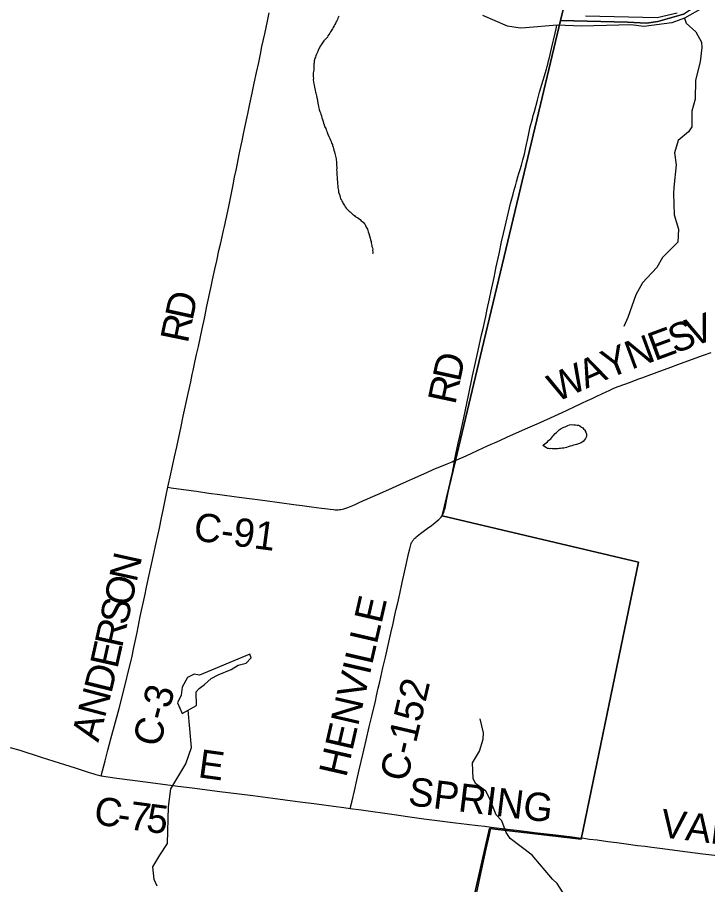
# Model space of a CAD drawing. Extents: x 1410790 to 1770854, y 448063 to 770588.
# Drawn here: x 1562316 to 1569641, y 582392 to 591590 of the extents above; entities that cross this region are included whole.
import ezdxf

# ---------------------------------------------------------------- set-up
doc = ezdxf.new("R2010")
doc.units = 0
for name, color, linetype in [('GM_X_County_Road', 7, 'Continuous'), ('GM_X_County_Road_Text', 7, 'Continuous'), ('GM_X_Major_River', 7, 'Continuous'), ('GM_X_Minor_Lake', 7, 'Continuous'), ('GM_X_Minor_River', 7, 'Continuous'), ('GM_X_Township', 7, 'Continuous'), ('GM_X_Township_Road', 7, 'Continuous')]:
    doc.layers.add(name, color=color, linetype=linetype)

msp = doc.modelspace()

# ---------------------------------------------------------------- linework, layer by layer
at = {"layer": 'GM_X_County_Road'}
for points in [[(1563913.9, 586607.1), (1563945.2, 586749.3), (1563955.8, 586797.3), (1563984.2, 586928.8), (1564007.2, 587034.5), (1564054, 587252.6), (1564076.9, 587361.8), (1564127.9, 587599.1), (1564155.7, 587723.9), (1564172.5, 587801), (1564182, 587845.7), (1564200.6, 587932.3), (1564218.5, 588015.5), (1564236.8, 588098.7), (1564278.9, 588287.6), (1564300.8, 588397.1), (1564328, 588528.7), (1564371.7, 588734), (1564387.4, 588807.7), (1564411.8, 588919.8), (1564431.1, 589009.1), (1564455.1, 589118.1), (1564474.2, 589199.8), (1564503.5, 589328.1), (1564513.6, 589372.5), (1564549.7, 589536.1), (1564562.9, 589603.1), (1564605.5, 589812.3), (1564621.1, 589895.6), (1564636.8, 589969.4), (1564650.7, 590040.2), (1564670.3, 590136.5), (1564691.4, 590232.6), (1564701.7, 590280.6), (1564716.8, 590354.3), (1564726.5, 590402.4), (1564740.3, 590469.8), (1564760.7, 590566), (1564783.5, 590672.4), (1564807.4, 590784), (1564830.6, 590893), (1564854.4, 591005.2), (1564877.3, 591111.1), (1564895.3, 591197.8), (1564911.4, 591281.5), (1564927.9, 591355.1), (1564941.1, 591415.9), (1564970.2, 591550.6), (1564987.3, 591637.4)], [(1566955.8, 586887.9), (1566968.7, 586956.3), (1566994.5, 587075), (1567010.6, 587148.7), (1567052.3, 587344.4), (1567102.2, 587578.6), (1567147, 587787.2), (1567178.5, 587928), (1567205.8, 588056.4), (1567242.7, 588223), (1567258, 588290.2), (1567285.8, 588418.4), (1567302.8, 588495.3), (1567327, 588604.1), (1567345.2, 588690.8), (1567367.6, 588800), (1567374.2, 588832.1), (1567397.9, 588944.4), (1567427.5, 589082.3), (1567454.9, 589210.7), (1567474.1, 589297), (1567502.3, 589418.4), (1567549.8, 589616.3), (1567576, 589714.6), (1567588.2, 589759), (1567600.5, 589803.2), (1567612, 589844.2), (1567627.3, 589897.7), (1567638.5, 589935.3), (1567650.8, 589976), (1567664.5, 590023.2), (1567680.1, 590080.1), (1567696, 590140.2), (1567716.8, 590225.9), (1567733.9, 590305.7), (1567759.3, 590427.6), (1567781.9, 590513.3), (1567791.4, 590548), (1567803.5, 590592.2), (1567835.3, 590712.5), (1567858.6, 590798), (1567894.5, 590924.4), (1567929.9, 591040), (1567937.9, 591068.6), (1567944.7, 591094.7), (1567954, 591129.7), (1567961.9, 591162.3), (1567985.7, 591259.6), (1568022.6, 591420.7), (1568033.2, 591467), (1568042.6, 591506.4)], [(1566955.8, 586887.9), (1567078, 586941.1), (1567260.1, 587024.1), (1567304.8, 587044.6), (1567343.5, 587062.4), (1567379.4, 587078.5), (1567436.4, 587103.9), (1567517.4, 587139.7), (1567733.2, 587235.3), (1567831.8, 587279.9), (1567972.3, 587343.4), (1568142.6, 587420.3), (1568166.2, 587431.4), (1568225.3, 587459.6), (1568305.2, 587497.5), (1568367.5, 587526.6), (1568415.1, 587548.8), (1568459.6, 587569.6), (1568518.7, 587598), (1568563, 587619.2), (1568595.7, 587634.2), (1568637.7, 587652.6), (1568680, 587670.2), (1568772, 587704.7), (1568839.5, 587729.5), (1568901, 587752.5), (1568953.3, 587771.9), (1569135.1, 587837.8), (1569221.1, 587870.2), (1569353.7, 587918.6), (1569402.9, 587936.3), (1569507.5, 587973.9), (1569598.8, 588007.3), (1569678.8, 588036.7)], [(1563913.9, 586607.1), (1563946.5, 586602.2), (1564079.4, 586582.4), (1564215.9, 586563.5), (1564349.1, 586545.7), (1564462.9, 586530.6), (1564641.6, 586505.7), (1564947.2, 586465.2), (1565096.7, 586445.1), (1565249.4, 586424.4), (1565337, 586412.6), (1565437.9, 586400.1), (1565541.9, 586385.9), (1565577.7, 586380.8), (1565636, 586373.3), (1565671.8, 586369.8), (1565688.8, 586368.7), (1565707.1, 586367.7), (1565719.8, 586368.3), (1565733.3, 586369.6), (1565750.2, 586371.6), (1565765.2, 586374.2), (1565780.9, 586378.1), (1565800.5, 586384.4), (1565823.7, 586392.5), (1565875.2, 586413.3), (1565908.3, 586427.4), (1565944.2, 586443.5), (1565983.1, 586460.9), (1566024.8, 586479.8), (1566063.4, 586497.5), (1566161.8, 586541.6), (1566296.7, 586601), (1566374.6, 586635.8), (1566446.6, 586667.6), (1566509.8, 586695), (1566629.7, 586748.1), (1566761.4, 586807.3), (1566770.3, 586811.4), (1566797.5, 586822.9), (1566876.1, 586855.9), (1566930.9, 586877.9), (1566949, 586885.1), (1566955.8, 586887.9)], [(1566826.7, 586307.6), (1566829.1, 586311.5), (1566836.2, 586324.1), (1566841.9, 586337.8), (1566850, 586365.6), (1566855.1, 586384.4), (1566859.1, 586403.3), (1566874.6, 586480.1), (1566913.8, 586673), (1566931.9, 586763), (1566950.5, 586859.5), (1566955.8, 586887.9)], [(1563206, 583546.9), (1563246.6, 583706.9), (1563275.3, 583817.9), (1563307.9, 583937.9), (1563395, 584261), (1563463.9, 584524.5), (1563496.5, 584658.4), (1563529.1, 584798.5), (1563552.8, 584908.1), (1563585.7, 585066.3), (1563620.9, 585235.8), (1563671.5, 585473.1), (1563683.8, 585530.9), (1563708.3, 585646.3), (1563742.6, 585806.6), (1563789.3, 586018), (1563823.2, 586171.8), (1563846.9, 586284.1), (1563863.1, 586364.5), (1563895.2, 586521.9), (1563913.9, 586607.1)], [(1565848.8, 583200.6), (1565867.8, 583281.7), (1565892.5, 583387.4), (1565919.7, 583502.2), (1565944.7, 583610.9), (1565982.9, 583773.5), (1566018.3, 583923.8), (1566050.9, 584064.4), (1566081.1, 584192.1), (1566115.6, 584339.1), (1566128.1, 584393.4), (1566146.5, 584476.6), (1566161.3, 584543.8), (1566194.4, 584691.1), (1566221.5, 584806.1), (1566244.4, 584901.8), (1566280.5, 585058.4), (1566303.3, 585160.8), (1566323.3, 585250.3), (1566337.1, 585314.3), (1566352.1, 585381.5), (1566374, 585477.5), (1566400.7, 585595.1), (1566425.8, 585705.6), (1566470.7, 585913), (1566479.8, 585952.3), (1566487.6, 585983.3), (1566491.1, 585996.1), (1566495.4, 586008.7), (1566500, 586019.6), (1566504, 586027.3), (1566508.6, 586034.5), (1566513.2, 586041.5), (1566518.3, 586048.5), (1566523.6, 586054.8), (1566529.7, 586061.7), (1566535.2, 586067.1), (1566543.2, 586074.5), (1566549.5, 586080.5), (1566557.2, 586087.4), (1566593.6, 586115.7), (1566664.8, 586168.1), (1566709.5, 586201.3), (1566744.7, 586229), (1566774.7, 586253.4), (1566787.9, 586263.7), (1566799.3, 586274.3), (1566812.5, 586288.6), (1566821.9, 586299.7), (1566826.7, 586307.6)], [(1562241.3, 583848.3), (1562341.4, 583816.9), (1562569.8, 583744.6), (1562704.4, 583702.6), (1562816.9, 583666.5), (1562929.4, 583630.6), (1563034.9, 583596.2), (1563077, 583582.7), (1563117.3, 583570.5), (1563148.7, 583561.8), (1563206, 583546.9)], [(1563206, 583546.9), (1563372.7, 583522.6), (1563674.9, 583481.9), (1564019.3, 583437.7), (1564172, 583417.6), (1564464.8, 583380.6), (1564670.1, 583356.1), (1564816.4, 583337.7), (1565027.7, 583310), (1565287.8, 583275.4), (1565489.4, 583248.3), (1565671.4, 583223.5), (1565782, 583209), (1565848.8, 583200.6)], [(1565848.8, 583200.6), (1565963.8, 583185.5), (1566314.4, 583137.8), (1566456.8, 583116.4), (1566630.6, 583090.8), (1566716, 583078.8), (1566966.6, 583047.2), (1567087.1, 583033.4), (1567201, 583020.4), (1567275.8, 583011.7), (1567343.1, 583003.4)], [(1567343.1, 583003.4), (1567516.1, 582982), (1567613.8, 582970.5), (1567724.5, 582956.9), (1567802.6, 582947.1), (1567900.1, 582934.9), (1568030.4, 582919.8), (1568115.1, 582909.9), (1568203.1, 582899.4), (1568274.7, 582890.7), (1568328.3, 582884)], [(1568328.3, 582884), (1568388.5, 582876.6), (1568469.8, 582866.3), (1568580.3, 582851.5), (1568677.7, 582837.8), (1568775.3, 582824.8), (1568895.5, 582809.4), (1568976.9, 582799.5), (1569048.5, 582790.5), (1569162.2, 582774.8), (1569345.5, 582751.4), (1569591.4, 582720.1), (1569901.7, 582683), (1570047.7, 582665), (1570157.3, 582650), (1570322.5, 582626.7), (1570430.7, 582613.1), (1570590.3, 582592.9), (1570871.8, 582557.9)]]:
    msp.add_lwpolyline(points, dxfattribs=at)
at = {"layer": 'GM_X_Major_River'}
for points in [[(1569621.7, 591707.7), (1569394, 591580.4), (1569260.4, 591531.4), (1568962.4, 591492.1), (1568826.4, 591511.3), (1568699.8, 591506.2), (1568302.2, 591495.2), (1568043.5, 591507.2), (1567707.7, 591478.9), (1567653.4, 591476.1), (1567517.4, 591497.3), (1567257.1, 591609.7)], [(1569319, 591634.4), (1569107, 591583.1), (1568346.8, 591602.6)]]:
    msp.add_lwpolyline(points, dxfattribs=at)
at = {"layer": 'GM_X_Minor_Lake'}
for points in [[(1567891.1, 587050.4), (1567897.6, 587057.6), (1567942, 587089.3), (1567952.2, 587103.3), (1567966.3, 587113.3), (1567976.3, 587119.2), (1567986.5, 587135.2), (1567998.6, 587147.2), (1568006.7, 587157.1), (1568024.9, 587177.1), (1568037, 587187), (1568051.2, 587203), (1568065.3, 587214.9), (1568077.4, 587222.8), (1568087.5, 587228.8), (1568101.6, 587236.7), (1568115.7, 587242.6), (1568127.8, 587246.6), (1568141.9, 587254.5), (1568156, 587262.4), (1568176.1, 587268.3), (1568198.2, 587272.2), (1568220.3, 587268), (1568240.4, 587269.8), (1568256.4, 587265.7), (1568270.4, 587265.6), (1568284.4, 587257.5), (1568302.4, 587245.3), (1568318.4, 587235.2), (1568324.4, 587225.1), (1568340.4, 587212.9), (1568342.3, 587202.9), (1568348.2, 587190.8), (1568354.1, 587168.7), (1568354, 587156.6), (1568353.9, 587144.6), (1568343.8, 587124.6), (1568333.6, 587110.6), (1568319.5, 587090.7), (1568297.3, 587078.8), (1568271.1, 587066.9), (1568251, 587061), (1568234.9, 587057.2), (1568216.8, 587051.3), (1568198.7, 587045.4), (1568180.6, 587041.5), (1568160.5, 587035.6), (1568144.4, 587029.7), (1568128.3, 587025.8), (1568114.2, 587019.9), (1568096.1, 587020), (1568080, 587016.1), (1568066, 587016.2), (1568051.9, 587014.3), (1568037.9, 587012.4), (1568027.8, 587012.5), (1568017.8, 587012.5), (1567999.7, 587012.7), (1567989.7, 587014.8), (1567975.7, 587016.9), (1567963.6, 587014.9), (1567953.6, 587017), (1567943.5, 587019.1), (1567931.6, 587025.2), (1567891.1, 587050.4)], [(1564218.7, 584293.3), (1564211.8, 584437.9), (1564246.6, 584473.2), (1564303.6, 584513.9), (1564371.1, 584578.6), (1564448, 584616.9), (1564585.5, 584675.8), (1564658.6, 584720.2), (1564745.2, 584742.3), (1564798.5, 584797.2), (1564781.3, 584837.7), (1564247.6, 584615.5), (1564191.7, 584622.9), (1564120.8, 584588.4), (1564066.6, 584487.4), (1564052.7, 584401.5), (1564016.9, 584322.1), (1564064.6, 584208.6)], [(1564064.6, 584208.6), (1564218.7, 584293.3)]]:
    msp.add_lwpolyline(points, dxfattribs=at)
at = {"layer": 'GM_X_Minor_River'}
for points in [[(1565727.8, 591602.8), (1565717.6, 591580.8), (1565713.5, 591566.8), (1565705.4, 591552.8), (1565697.3, 591538.8), (1565691.2, 591524.8), (1565685.1, 591512.8), (1565676.9, 591498.8), (1565666.8, 591480.8), (1565660.7, 591466.8), (1565654.6, 591456.8), (1565646.5, 591446.8), (1565640.4, 591434.8), (1565632.2, 591420.9), (1565622.1, 591406.9), (1565612, 591392.9), (1565605.9, 591380.9), (1565593.7, 591366.9), (1565583.6, 591355), (1565569.5, 591339), (1565561.4, 591329), (1565555.3, 591319.1), (1565539.1, 591297.1), (1565528.9, 591283.1), (1565524.9, 591273.1), (1565518.7, 591261.1), (1565510.6, 591249.1), (1565506.6, 591239.1), (1565504.5, 591227.1), (1565496.3, 591213.1), (1565490.2, 591199.1), (1565484.1, 591183.1), (1565480, 591169.1), (1565473.9, 591155.1), (1565469.7, 591139.1), (1565465.7, 591129.1), (1565465.6, 591119), (1565465.5, 591109), (1565461.4, 591097), (1565461.4, 591084.9), (1565461.3, 591074.9), (1565461.2, 591060.8), (1565461.1, 591044.8), (1565461, 591030.8), (1565458.9, 591014.7), (1565456.8, 591000.7), (1565456.7, 590990.6), (1565454.5, 590968.6), (1565456.5, 590958.5), (1565458.4, 590944.5), (1565456.3, 590926.4), (1565458.1, 590904.3), (1565462, 590884.2), (1565465.9, 590870.2), (1565467.8, 590850.1), (1565471.7, 590832), (1565477.6, 590815.9), (1565479.5, 590797.8), (1565483.4, 590785.8), (1565487.4, 590771.7), (1565491.3, 590757.6), (1565493.2, 590739.5), (1565497.1, 590727.4), (1565504.8, 590679.2), (1565506.7, 590663.2), (1565510.6, 590647.1), (1565514.5, 590627), (1565520.4, 590610.9), (1565526.3, 590592.8), (1565532.2, 590578.7), (1565536.1, 590562.6), (1565542, 590546.5), (1565547.9, 590524.4), (1565553.8, 590506.3), (1565559.7, 590484.2)], [(1569394, 591580.4), (1569414.3, 591528.8), (1569516.5, 591436.1), (1569574.3, 591326.5), (1569581.1, 591268.2), (1569561.8, 591116.2), (1569511.6, 590922.8), (1569509.3, 590722.3), (1569472.5, 590594.8), (1569475, 590430.2), (1569439.8, 590376.9), (1569327.6, 590283.2), (1569290.8, 590153.7), (1569306, 590025), (1569280.9, 589786.9), (1569279.5, 589722.8), (1569286.7, 589495.9), (1569333.5, 589342.4), (1569324.6, 589206.2), (1569162.8, 589043.5), (1569100.4, 588936.7), (1568948.7, 588773.8), (1568877.8, 588647), (1568794.6, 588408.3), (1568751.6, 588312.6)], [(1565559.7, 590484.2), (1565565.6, 590466.1), (1565573.5, 590449.9), (1565575.4, 590433.9), (1565583.4, 590421.8), (1565589.3, 590409.7), (1565593.2, 590395.6), (1565599.2, 590383.5), (1565605.1, 590369.4), (1565611, 590351.3), (1565622.9, 590325.2), (1565630.8, 590305), (1565638.7, 590288.9), (1565644.6, 590272.8), (1565650.5, 590256.7), (1565658.5, 590240.6), (1565660.4, 590230.6), (1565668.3, 590212.4), (1565670.2, 590198.4), (1565674.1, 590180.3), (1565682, 590162.2), (1565685.9, 590146.1), (1565689.8, 590130), (1565691.7, 590115.9), (1565695.7, 590103.9), (1565697.6, 590089.8), (1565699.5, 590073.7), (1565701.4, 590061.7), (1565703.3, 590049.6), (1565703.2, 590033.6), (1565703.1, 590019.5), (1565705, 590001.4), (1565704.9, 589989.4), (1565702.8, 589971.4), (1565704.7, 589957.3), (1565706.6, 589943.2), (1565704.5, 589927.2), (1565710.2, 589883), (1565708.1, 589867), (1565712, 589848.9), (1565713.9, 589824.8), (1565717.8, 589804.7), (1565717.6, 589784.6), (1565721.5, 589768.5), (1565725.4, 589754.4), (1565725.3, 589734.4), (1565731.2, 589718.3), (1565737.1, 589700.2), (1565741, 589684.1), (1565746.9, 589666), (1565754.9, 589653.9), (1565760.8, 589641.8), (1565768.8, 589627.7), (1565774.7, 589615.6), (1565780.7, 589605.5), (1565788.6, 589593.4), (1565794.5, 589579.3), (1565806.5, 589567.2), (1565816.5, 589555.1), (1565826.4, 589545), (1565836.4, 589534.9), (1565846.4, 589526.8), (1565864.3, 589510.6), (1565874.3, 589500.5), (1565884.3, 589494.4), (1565894.3, 589488.3), (1565902.3, 589478.2), (1565914.3, 589472.1), (1565926.3, 589466), (1565944.3, 589451.8), (1565954.3, 589447.7), (1565966.2, 589433.6), (1565976.2, 589425.5), (1565986.2, 589419.4), (1565998.1, 589401.3), (1566006.1, 589391.2), (1566012, 589381.1), (1566018, 589365), (1566025.9, 589354.9), (1566029.9, 589344.8), (1566033.8, 589330.8), (1566037.7, 589316.7), (1566045.6, 589296.6), (1566059.3, 589246.3), (1566065.2, 589230.2), (1566069.1, 589214.1), (1566071, 589198), (1566075, 589184), (1566078.9, 589171.9), (1566078.8, 589159.9), (1566084.7, 589143.8), (1566086.6, 589129.7), (1566084.5, 589115.7), (1566086.5, 589103.6), (1566088.4, 589093.6), (1566086.3, 589083.5)], [(1563801, 582375.4), (1563768.5, 582446.3), (1563755.4, 582583.1), (1563828.1, 582705.7), (1563910.9, 582828.2), (1563919.2, 583217.1), (1563945.3, 583409.1), (1564103.2, 583672.2), (1564165, 583845.2), (1564128.4, 584243.7)], [(1568163.3, 582217), (1568045.1, 582404.4), (1567994, 582451.7), (1567779, 582703.5), (1567546.4, 582881.4), (1567501.7, 582944.6), (1567458.3, 583070), (1567395.5, 583133.7), (1567325.2, 583309.8), (1567288.7, 583382.9), (1567176.2, 583463.8), (1567151.3, 583518.5), (1567146.9, 583685.1), (1567221.6, 583809.7), (1567258.4, 583935.2), (1567261.8, 584003.3), (1567226.9, 584150.6)]]:
    msp.add_lwpolyline(points, dxfattribs=at)
at = {"layer": 'GM_X_Township'}
for points in [[(1568287, 592416.8), (1568080.9, 591556), (1567885.2, 590738.6), (1567559.7, 589379.4), (1567265.9, 588152.5), (1566963.9, 586891.4), (1566823.2, 586303.6), (1568906.4, 585811.5), (1568300.4, 582874.8), (1567328, 582988.6), (1566849.4, 580884.8)], [(1569383.7, 591622.7), (1569112.2, 591544.6), (1568993.7, 591527.4), (1568789.1, 591539.1), (1568080.9, 591556), (1568287, 592416.8)], [(1566849.4, 580884.8), (1567328, 582988.6), (1568300.4, 582874.8), (1568906.4, 585811.5), (1566823.2, 586303.6), (1566963.9, 586891.4), (1567265.9, 588152.5), (1567559.7, 589379.4), (1567885.2, 590738.6), (1568080.9, 591556), (1568789.1, 591539.1), (1568993.7, 591527.4), (1569112.2, 591544.6), (1569383.7, 591622.7), (1569593.4, 591763.5), (1569704.6, 591866.9)]]:
    msp.add_lwpolyline(points, dxfattribs=at)
at = {"layer": 'GM_X_Township_Road'}
msp.add_lwpolyline([(1566891.5, 580915.9), (1566889.6, 580934.6), (1566890.8, 580954.6), (1566893.6, 580975.9), (1566897.3, 580999.4), (1566918.7, 581091.7), (1566953.6, 581248.5), (1566985.6, 581392.5), (1567008, 581495.1), (1567053.7, 581700), (1567115.2, 581975.2), (1567137.8, 582077.7), (1567208.6, 582391.2), (1567227.7, 582474.3), (1567292.1, 582769), (1567326.1, 582922.5), (1567337, 582974), (1567343.1, 583003.4)], dxfattribs=at)

# ---------------------------------------------------------------- texts
at = {"layer": 'GM_X_County_Road_Text'}
for s, rotation, p in [('D', 77.72485, (1564173.9, 588365.9)), ('V', 20.25388, (1569479.4, 588091.4)), ('R', 78.33566, (1564124.3, 588125.4)), ('S', 20.25281, (1569289.5, 588021.3)), ('E', 20.24856, (1569078.9, 587943.6)), ('N', 20.30833, (1568831.4, 587852)), ('Y', 21.74391, (1568588, 587755)), ('D', 77.76199, (1567013.2, 587715.5)), ('A', 23.99836, (1568349.7, 587648.8)), ('W', 24.64567, (1568034.6, 587504.2)), ('R', 78.08078, (1566962.4, 587474.8)), ('C-91', 352.44914, (1564175.7, 586045.6)), ('N', 77.52974, (1563580.2, 585590.2)), ('O', 77.53124, (1563523.2, 585332.4)), ('S', 77.53355, (1563479.5, 585134.8)), ('HENVILLE', 77.05644, (1565805.7, 583521.4)), ('R', 77.53255, (1563426.3, 584894.2)), ('E', 77.35323, (1563376.9, 584674.3)), ('D', 76.21684, (1563312.6, 584411.5)), ('C-3', 75.18589, (1563824.8, 583839.6)), ('C-152', 76.96426, (1566451.1, 583472.9)), ('N', 75.17782, (1563243.5, 584150.6)), ('A', 75.0674, (1563175.3, 583894.9)), ('E', 352.18454, (1564225, 583532.5)), ('SPRING', 353.04153, (1566453.8, 583236.8)), ('C', 350.58452, (1563115.1, 583039.6)), ('7', 352.42569, (1563490.6, 582980.6)), ('5', 352.54322, (1563674.4, 582956.2)), ('VALLEY', 352.83223, (1569129.9, 582899.2)), ('-', 352.02018, (1563366.3, 582998))]:
    msp.add_text(s, height=300, rotation=rotation, dxfattribs=at).set_placement(p)

doc.saveas('drawing.dxf')
